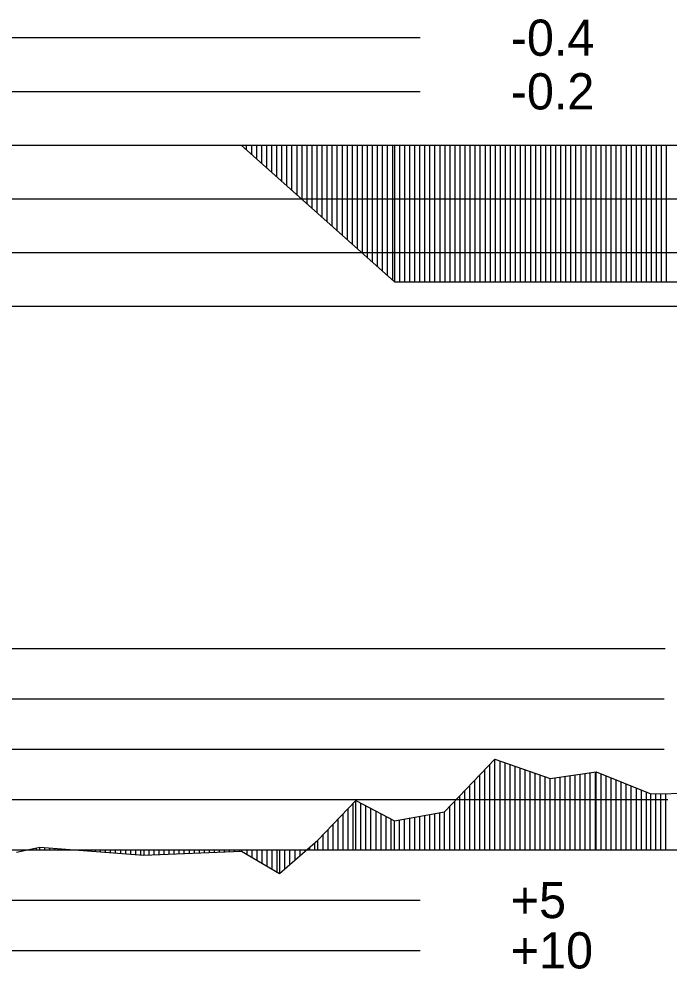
# Model space of a CAD drawing. Extents: x 2 to 10148, y 0 to 380.
# Drawn here: x 3438.09 to 3470.4, y 236.07 to 283.26 of the extents above; entities that cross this region are included whole.
import ezdxf

# ---------------------------------------------------------------- set-up
doc = ezdxf.new("R2010")
doc.units = 0
for name, color, linetype in [('POSUN_CARA', 7, 'Continuous'), ('POSUN_RASTR', 7, 'Continuous'), ('POSUN_TEXT', 7, 'Continuous'), ('ZRYCHL_CARA', 7, 'Continuous'), ('ZRYCHL_RASTR', 7, 'Continuous'), ('ZRYCHL_TEXT', 7, 'Continuous')]:
    doc.layers.add(name, color=color, linetype=linetype)

msp = doc.modelspace()

# ---------------------------------------------------------------- linework, layer by layer
at = {"layer": 'POSUN_CARA'}
for p, q in [((3459.217, 243.884), (3461.715, 246.503)), ((3461.715, 246.503), (3464.448, 245.532)), ((3461.715, 242), (3461.715, 246.503)), ((3461.965, 242), (3461.965, 246.414)), ((3462.215, 242), (3462.215, 246.325)), ((3461.217, 242), (3461.217, 245.981)), ((3461.467, 242), (3461.467, 246.243)), ((3462.465, 242), (3462.465, 246.237)), ((3462.715, 242), (3462.715, 246.148)), ((3462.965, 242), (3462.965, 246.059)), ((3463.215, 242), (3463.215, 245.97)), ((3463.465, 242), (3463.465, 245.881)), ((3464.448, 245.532), (3466.733, 245.869)), ((3466.698, 242), (3466.698, 245.864)), ((3466.733, 245.869), (3469.45, 244.781)), ((3466.733, 242), (3466.733, 245.869)), ((3460.717, 242), (3460.717, 245.457)), ((3460.967, 242), (3460.967, 245.719)), ((3463.715, 242), (3463.715, 245.793)), ((3463.965, 242), (3463.965, 245.704)), ((3464.215, 242), (3464.215, 245.615)), ((3464.448, 242), (3464.448, 245.532)), ((3464.698, 242), (3464.698, 245.569)), ((3464.948, 242), (3464.948, 245.606)), ((3465.198, 242), (3465.198, 245.643)), ((3465.448, 242), (3465.448, 245.68)), ((3465.698, 242), (3465.698, 245.717)), ((3465.948, 242), (3465.948, 245.754)), ((3466.198, 242), (3466.198, 245.79)), ((3466.448, 242), (3466.448, 245.827)), ((3466.983, 242), (3466.983, 245.769)), ((3467.233, 242), (3467.233, 245.669)), ((3467.483, 242), (3467.483, 245.569)), ((3467.733, 242), (3467.733, 245.469)), ((3467.983, 242), (3467.983, 245.369)), ((3460.217, 242), (3460.217, 244.933)), ((3460.467, 242), (3460.467, 245.195)), ((3468.233, 242), (3468.233, 245.268)), ((3468.483, 242), (3468.483, 245.168)), ((3468.733, 242), (3468.733, 245.068)), ((3468.983, 242), (3468.983, 244.968)), ((3452.928, 242.472), (3454.809, 244.439)), ((3454.809, 244.439), (3456.731, 243.436)), ((3454.809, 242), (3454.809, 244.439)), ((3459.967, 242), (3459.967, 244.671)), ((3469.233, 242), (3469.233, 244.868)), ((3469.45, 244.781), (3472.141, 244.811)), ((3469.45, 242), (3469.45, 244.781)), ((3469.7, 242), (3469.7, 244.784)), ((3469.95, 242), (3469.95, 244.787)), ((3470.2, 242), (3470.2, 244.789)), ((3454.428, 242), (3454.428, 244.04)), ((3454.678, 242), (3454.678, 244.301)), ((3455.059, 242), (3455.059, 244.309)), ((3455.309, 242), (3455.309, 244.178)), ((3455.559, 242), (3455.559, 244.048)), ((3459.467, 242), (3459.467, 244.146)), ((3459.717, 242), (3459.717, 244.408)), ((3453.928, 242), (3453.928, 243.517)), ((3454.178, 242), (3454.178, 243.779)), ((3455.809, 242), (3455.809, 243.917)), ((3456.059, 242), (3456.059, 243.787)), ((3456.309, 242), (3456.309, 243.656)), ((3456.559, 242), (3456.559, 243.526)), ((3456.731, 243.436), (3459.217, 243.884)), ((3456.981, 242), (3456.981, 243.481)), ((3457.231, 242), (3457.231, 243.526)), ((3457.481, 242), (3457.481, 243.571)), ((3457.731, 242), (3457.731, 243.616)), ((3457.981, 242), (3457.981, 243.661)), ((3458.231, 242), (3458.231, 243.707)), ((3458.481, 242), (3458.481, 243.752)), ((3458.731, 242), (3458.731, 243.797)), ((3458.981, 242), (3458.981, 243.842)), ((3459.217, 242), (3459.217, 243.884)), ((3453.678, 242), (3453.678, 243.256)), ((3456.731, 242), (3456.731, 243.436)), ((3453.178, 242), (3453.178, 242.733)), ((3453.428, 242), (3453.428, 242.995)), ((3437.956, 241.882), (3439.116, 242.128)), ((3438.956, 242), (3438.956, 242.094)), ((3439.116, 242.128), (3444.275, 241.736)), ((3439.116, 242), (3439.116, 242.128)), ((3439.366, 242), (3439.366, 242.109)), ((3439.616, 242), (3439.616, 242.09)), ((3439.866, 242), (3439.866, 242.071)), ((3451.022, 240.821), (3452.928, 242.472)), ((3452.522, 242), (3452.522, 242.12)), ((3452.772, 242), (3452.772, 242.337)), ((3452.928, 242), (3452.928, 242.472)), ((3438.206, 242), (3438.206, 241.935)), ((3438.456, 242), (3438.456, 241.988)), ((3438.706, 242), (3438.706, 242.041)), ((3440.116, 242), (3440.116, 242.052)), ((3440.366, 242), (3440.366, 242.033)), ((3440.616, 242), (3440.616, 242.014)), ((3440.866, 242), (3440.866, 241.995)), ((3441.116, 242), (3441.116, 241.976)), ((3441.366, 242), (3441.366, 241.957)), ((3441.616, 242), (3441.616, 241.938)), ((3441.866, 242), (3441.866, 241.919)), ((3442.116, 242), (3442.116, 241.9)), ((3442.366, 242), (3442.366, 241.881)), ((3442.616, 242), (3442.616, 241.862)), ((3442.866, 242), (3442.866, 241.843)), ((3443.116, 242), (3443.116, 241.824)), ((3443.366, 242), (3443.366, 241.805)), ((3443.616, 242), (3443.616, 241.786)), ((3443.866, 242), (3443.866, 241.767)), ((3444.116, 242), (3444.116, 241.748)), ((3444.275, 242), (3444.275, 241.736)), ((3444.275, 241.736), (3449.139, 241.927)), ((3444.525, 242), (3444.525, 241.745)), ((3444.775, 242), (3444.775, 241.755)), ((3445.025, 242), (3445.025, 241.765)), ((3445.275, 242), (3445.275, 241.775)), ((3445.525, 242), (3445.525, 241.785)), ((3445.775, 242), (3445.775, 241.795)), ((3446.025, 242), (3446.025, 241.804)), ((3446.275, 242), (3446.275, 241.814)), ((3446.525, 242), (3446.525, 241.824)), ((3446.775, 242), (3446.775, 241.834)), ((3447.025, 242), (3447.025, 241.844)), ((3447.275, 242), (3447.275, 241.853)), ((3447.525, 242), (3447.525, 241.863)), ((3447.775, 242), (3447.775, 241.873)), ((3448.025, 242), (3448.025, 241.883)), ((3448.275, 242), (3448.275, 241.893)), ((3448.525, 242), (3448.525, 241.902)), ((3448.775, 242), (3448.775, 241.912)), ((3449.025, 242), (3449.025, 241.922)), ((3449.139, 242), (3449.139, 241.927)), ((3449.139, 241.927), (3451.022, 240.821)), ((3449.389, 242), (3449.389, 241.78)), ((3449.639, 242), (3449.639, 241.633)), ((3449.889, 242), (3449.889, 241.486)), ((3450.139, 242), (3450.139, 241.339)), ((3450.389, 242), (3450.389, 241.192)), ((3450.639, 242), (3450.639, 241.045)), ((3450.889, 242), (3450.889, 240.899)), ((3451.022, 242), (3451.022, 240.821)), ((3451.272, 242), (3451.272, 241.037)), ((3451.522, 242), (3451.522, 241.254)), ((3451.772, 242), (3451.772, 241.471)), ((3452.022, 242), (3452.022, 241.687)), ((3452.272, 242), (3452.272, 241.904))]:
    msp.add_line(p, q, dxfattribs=at)
at = {"layer": 'POSUN_RASTR'}
for p, q in [((3258.848, 252), (3470.165, 252)), ((3258.76, 249.5), (3470.119, 249.5)), ((3258.804, 247), (3470.119, 247)), ((3258.804, 244.5), (3470.303, 244.5)), ((3155.54, 242), (4045.764, 242)), ((3256.338, 239.5), (3458, 239.5)), ((3256.443, 237), (3458, 237))]:
    msp.add_line(p, q, dxfattribs=at)
at = {"layer": 'ZRYCHL_CARA'}
for p, q in [((3155.54, 277), (4045.764, 277)), ((3449.121, 277), (3456.721, 270.202)), ((3449.371, 277), (3449.371, 276.776)), ((3449.621, 277), (3449.621, 276.553)), ((3449.871, 277), (3449.871, 276.329)), ((3450.121, 277), (3450.121, 276.106)), ((3450.371, 277), (3450.371, 275.882)), ((3450.621, 277), (3450.621, 275.658)), ((3450.871, 277), (3450.871, 275.435)), ((3451.121, 277), (3451.121, 275.211)), ((3451.371, 277), (3451.371, 274.987)), ((3451.621, 277), (3451.621, 274.764)), ((3451.871, 277), (3451.871, 274.54)), ((3452.121, 277), (3452.121, 274.317)), ((3452.371, 277), (3452.371, 274.093)), ((3452.621, 277), (3452.621, 273.869)), ((3452.871, 277), (3452.871, 273.646)), ((3453.121, 277), (3453.121, 273.422)), ((3453.371, 277), (3453.371, 273.198)), ((3453.621, 277), (3453.621, 272.975)), ((3453.871, 277), (3453.871, 272.751)), ((3454.121, 277), (3454.121, 272.528)), ((3454.371, 277), (3454.371, 272.304)), ((3454.621, 277), (3454.621, 272.08)), ((3454.871, 277), (3454.871, 271.857)), ((3455.121, 277), (3455.121, 271.633)), ((3455.371, 277), (3455.371, 271.409)), ((3455.621, 277), (3455.621, 271.186)), ((3455.871, 277), (3455.871, 270.962)), ((3456.121, 277), (3456.121, 270.739)), ((3456.371, 277), (3456.371, 270.515)), ((3456.621, 277), (3456.621, 270.291)), ((3456.721, 277), (3456.721, 270.202)), ((3456.971, 277), (3456.971, 270.202)), ((3457.221, 277), (3457.221, 270.202)), ((3457.471, 277), (3457.471, 270.202)), ((3457.721, 277), (3457.721, 270.202)), ((3457.971, 277), (3457.971, 270.202)), ((3458.221, 277), (3458.221, 270.202)), ((3458.471, 277), (3458.471, 270.202)), ((3458.721, 277), (3458.721, 270.202)), ((3458.971, 277), (3458.971, 270.202)), ((3459.221, 277), (3459.221, 270.202)), ((3459.471, 277), (3459.471, 270.202)), ((3459.721, 277), (3459.721, 270.202)), ((3459.971, 277), (3459.971, 270.202)), ((3460.221, 277), (3460.221, 270.202)), ((3460.471, 277), (3460.471, 270.202)), ((3460.721, 277), (3460.721, 270.202)), ((3460.971, 277), (3460.971, 270.202)), ((3461.221, 277), (3461.221, 270.202)), ((3461.471, 277), (3461.471, 270.202)), ((3461.721, 277), (3461.721, 270.202)), ((3461.971, 277), (3461.971, 270.202)), ((3462.221, 277), (3462.221, 270.202)), ((3462.471, 277), (3462.471, 270.202)), ((3462.721, 277), (3462.721, 270.202)), ((3462.971, 277), (3462.971, 270.202)), ((3463.221, 277), (3463.221, 270.202)), ((3463.471, 277), (3463.471, 270.202)), ((3463.721, 277), (3463.721, 270.202)), ((3463.971, 277), (3463.971, 270.202)), ((3464.221, 277), (3464.221, 270.202)), ((3464.471, 277), (3464.471, 270.202)), ((3464.721, 277), (3464.721, 270.202)), ((3464.971, 277), (3464.971, 270.202)), ((3465.221, 277), (3465.221, 270.202)), ((3465.471, 277), (3465.471, 270.202)), ((3465.721, 277), (3465.721, 270.202)), ((3465.971, 277), (3465.971, 270.202)), ((3466.221, 277), (3466.221, 270.202)), ((3466.471, 277), (3466.471, 270.202)), ((3466.721, 277), (3466.721, 270.202)), ((3466.971, 277), (3466.971, 270.202)), ((3467.221, 277), (3467.221, 270.202)), ((3467.471, 277), (3467.471, 270.202)), ((3467.721, 277), (3467.721, 270.202)), ((3467.971, 277), (3467.971, 270.202)), ((3468.221, 277), (3468.221, 270.202)), ((3468.471, 277), (3468.471, 270.202)), ((3468.721, 277), (3468.721, 270.202)), ((3468.971, 277), (3468.971, 270.202)), ((3469.221, 277), (3469.221, 270.202)), ((3469.471, 277), (3469.471, 270.202)), ((3469.721, 277), (3469.721, 270.202)), ((3469.971, 277), (3469.971, 270.202)), ((3470.221, 277), (3470.221, 270.202)), ((3456.721, 270.202), (3482.144, 270.202))]:
    msp.add_line(p, q, dxfattribs=at)
at = {"layer": 'ZRYCHL_RASTR'}
for p, q in [((3262, 282.333), (3458, 282.333)), ((3262, 279.667), (3458, 279.667)), ((3262, 274.333), (3458, 274.333)), ((3458, 274.333), (3668, 274.333)), ((3262, 271.667), (3458, 271.667)), ((3458, 271.667), (3668, 271.667)), ((3262, 269), (3458, 269)), ((3458, 269), (3668, 269))]:
    msp.add_line(p, q, dxfattribs=at)

# ---------------------------------------------------------------- texts
at = {"layer": 'POSUN_TEXT'}
for s, p in [('+5', (3462.5, 238.6)), ('+10', (3462.5, 236.1))]:
    msp.add_text(s, height=1.8, dxfattribs=at).set_placement(p)
at = {"layer": 'ZRYCHL_TEXT'}
for s, p in [('-0.4', (3462.5, 281.433)), ('-0.2', (3462.5, 278.767))]:
    msp.add_text(s, height=1.8, dxfattribs=at).set_placement(p)

doc.saveas('drawing.dxf')
